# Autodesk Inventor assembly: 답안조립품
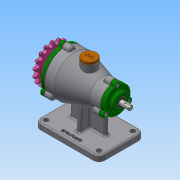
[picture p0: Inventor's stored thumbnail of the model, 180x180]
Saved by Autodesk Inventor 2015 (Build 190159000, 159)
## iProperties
Created: 2020-03
Part Number: 답안조립품
Document SubType Name: Assembly
Designer: user
Author: user
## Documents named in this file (15)
- C:\Users\user\Desktop\700306V1008\답안조립품.iam
- C:\Users\user\Desktop\700306V1008\본체.ipt
- C:\Users\user\Desktop\700306V1008\개스킷 A.ipt
- C:\Users\user\Desktop\700306V1008\개스킷 B.ipt
- C:\Users\user\Desktop\700306V1008\뒤커버.ipt
- C:\Users\user\Desktop\700306V1008\마개.ipt
- C:\Users\user\Desktop\700306V1008\베어링 6200.ipt
- C:\Users\user\Desktop\700306V1008\베어링 6203.ipt
- C:\Users\user\Desktop\700306V1008\볼트 M5.ipt
- C:\Users\user\Desktop\700306V1008\스프로킷.ipt
- C:\Users\user\Desktop\700306V1008\앞커버.ipt
- C:\Users\user\Desktop\700306V1008\오일 실 10 20 7.ipt
- C:\Users\user\Desktop\700306V1008\오일 실 17 30 8.ipt
- C:\Users\user\Desktop\700306V1008\축.ipt
- C:\Users\user\Desktop\700306V1008\키 4x4x14.ipt
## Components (2 placed, 2 different names)
1. 개스킷 A:1
2. 개스킷 B:1
